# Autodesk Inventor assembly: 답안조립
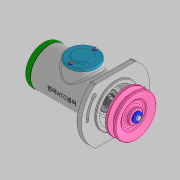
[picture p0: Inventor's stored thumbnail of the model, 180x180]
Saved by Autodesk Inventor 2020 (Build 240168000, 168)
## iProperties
Created: 2022-05
Part Number: 답안조립
Document SubType Name: Assembly
Designer: User
Author: User
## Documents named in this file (22)
- C:\Users\User\Desktop\720506V1033\답안조립.iam
- C:\Users\User\Desktop\720506V1033\본체.ipt
- C:\Users\User\Desktop\720506V1033\V-벨트풀리.ipt
- C:\Users\User\Desktop\720506V1033\개스킷.ipt
- C:\Users\User\Desktop\720506V1033\너트 M10.ipt
- C:\Users\User\Desktop\720506V1033\멈춤나사 M3.ipt
- C:\Users\User\Desktop\720506V1033\멈춤링 15 x 1.ipt
- C:\Users\User\Desktop\720506V1033\멈춤링 35 x 1.6.ipt
- C:\Users\User\Desktop\720506V1033\베어링 6202.ipt
- C:\Users\User\Desktop\720506V1033\볼트 M4 x 10.ipt
- C:\Users\User\Desktop\720506V1033\부시1.ipt
- C:\Users\User\Desktop\720506V1033\부시2.ipt
- C:\Users\User\Desktop\720506V1033\사이드 커버.ipt
- 사이드 커버.ipt
- C:\Users\User\Desktop\720506V1033\십자볼트 M3 x 10.ipt
- C:\Users\User\Desktop\720506V1033\오일 실 15 x 30 x 7.ipt
- C:\Users\User\Desktop\720506V1033\와셔 3 x 6.ipt
- C:\Users\User\Desktop\720506V1033\와셔 4 x 16.ipt
- C:\Users\User\Desktop\720506V1033\와셔 10 x 21.ipt
- C:\Users\User\Desktop\720506V1033\축.ipt
- C:\Users\User\Desktop\720506V1033\키 4 x 4.ipt
- C:\Users\User\Desktop\720506V1033\탑 커버.ipt
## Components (3 placed, 3 different names)
1. V-벨트풀리:1
2. 개스킷:1
3. ISO 4017 M4 x 10:1 — 각도:4, 각도:5
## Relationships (2: Angle 2)
- 각도:4 [Angle]: ISO 4017 M4 x 10:1
- 각도:5 [Angle]: ISO 4017 M4 x 10:1
